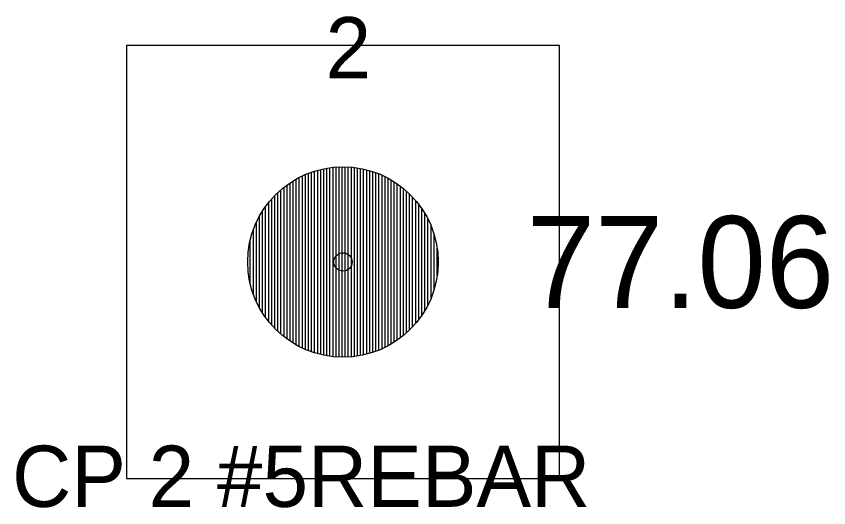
# Model space of a CAD drawing. Extents: x 2505249 to 2506333, y 912937 to 914171.
# Drawn here: x 2506319.57 to 2506332.83, y 914162.56 to 914170.59 of the extents above; entities that cross this region are included whole.
import ezdxf

# ---------------------------------------------------------------- set-up
doc = ezdxf.new("R2010")
doc.units = 0
for name, color, linetype in [('RD_HC_Survey', 7, 'Continuous'), ('RD_HC_Survey_ELEV', 7, 'Continuous'), ('RD_HC_Survey_txCode', 7, 'Continuous'), ('RD_SMD_Locator', 7, 'Continuous')]:
    doc.layers.add(name, color=color, linetype=linetype)

msp = doc.modelspace()

# ---------------------------------------------------------------- linework, layer by layer
at = {"layer": 'RD_HC_Survey'}
for p, q in [((2506324.489, 914165.072), (2506324.489, 914168.071)), ((2506324.539, 914165.06), (2506324.539, 914168.083)), ((2506324.589, 914165.049), (2506324.589, 914168.094)), ((2506324.639, 914165.039), (2506324.639, 914168.104)), ((2506324.689, 914165.031), (2506324.689, 914168.112)), ((2506324.739, 914165.025), (2506324.739, 914168.118)), ((2506324.789, 914165.021), (2506324.789, 914168.122)), ((2506324.839, 914165.018), (2506324.839, 914168.125)), ((2506324.889, 914165.017), (2506324.889, 914168.126)), ((2506324.939, 914165.017), (2506324.939, 914168.126)), ((2506324.989, 914165.019), (2506324.989, 914168.124)), ((2506325.039, 914165.023), (2506325.039, 914168.12)), ((2506325.089, 914165.028), (2506325.089, 914168.115)), ((2506325.139, 914165.035), (2506325.139, 914168.108)), ((2506325.189, 914165.044), (2506325.189, 914168.099)), ((2506325.239, 914165.054), (2506325.239, 914168.089)), ((2506325.289, 914165.066), (2506325.289, 914168.077)), ((2506324.189, 914165.189), (2506324.189, 914167.954)), ((2506324.239, 914165.165), (2506324.239, 914167.978)), ((2506324.289, 914165.142), (2506324.289, 914168.001)), ((2506324.339, 914165.122), (2506324.339, 914168.021)), ((2506324.389, 914165.104), (2506324.389, 914168.039)), ((2506324.439, 914165.087), (2506324.439, 914168.056)), ((2506325.339, 914165.08), (2506325.339, 914168.063)), ((2506325.389, 914165.096), (2506325.389, 914168.047)), ((2506325.439, 914165.113), (2506325.439, 914168.03)), ((2506325.489, 914165.132), (2506325.489, 914168.011)), ((2506325.539, 914165.154), (2506325.539, 914167.989)), ((2506325.589, 914165.177), (2506325.589, 914167.966)), ((2506325.639, 914165.203), (2506325.639, 914167.94)), ((2506323.989, 914165.312), (2506323.989, 914167.831)), ((2506324.039, 914165.278), (2506324.039, 914167.865)), ((2506324.089, 914165.246), (2506324.089, 914167.897)), ((2506324.139, 914165.216), (2506324.139, 914167.927)), ((2506325.689, 914165.231), (2506325.689, 914167.912)), ((2506325.739, 914165.262), (2506325.739, 914167.881)), ((2506325.789, 914165.296), (2506325.789, 914167.847)), ((2506325.839, 914165.332), (2506325.839, 914167.811)), ((2506323.839, 914165.436), (2506323.839, 914167.707)), ((2506323.889, 914165.391), (2506323.889, 914167.752)), ((2506323.939, 914165.35), (2506323.939, 914167.793)), ((2506325.889, 914165.371), (2506325.889, 914167.772)), ((2506325.939, 914165.414), (2506325.939, 914167.729)), ((2506325.989, 914165.461), (2506325.989, 914167.682)), ((2506323.689, 914165.598), (2506323.689, 914167.545)), ((2506323.739, 914165.539), (2506323.739, 914167.604)), ((2506323.789, 914165.485), (2506323.789, 914167.658)), ((2506326.039, 914165.513), (2506326.039, 914167.63)), ((2506326.089, 914165.569), (2506326.089, 914167.574)), ((2506323.639, 914165.664), (2506323.639, 914167.479)), ((2506326.139, 914165.631), (2506326.139, 914167.512)), ((2506326.189, 914165.701), (2506326.189, 914167.442)), ((2506323.539, 914165.822), (2506323.539, 914167.321)), ((2506323.589, 914165.737), (2506323.589, 914167.406)), ((2506326.239, 914165.78), (2506326.239, 914167.363)), ((2506323.489, 914165.921), (2506323.489, 914167.222)), ((2506326.289, 914165.872), (2506326.289, 914167.271)), ((2506326.339, 914165.981), (2506326.339, 914167.162)), ((2506323.439, 914166.043), (2506323.439, 914167.1)), ((2506326.389, 914166.122), (2506326.389, 914167.021)), ((2506323.389, 914166.21), (2506323.389, 914166.933)), ((2506326.439, 914166.346), (2506326.439, 914166.797))]:
    msp.add_line(p, q, dxfattribs=at)
msp.add_lwpolyline([(2506328.437, 914170.107), (2506321.366, 914170.107), (2506321.366, 914163.036), (2506328.437, 914163.036)], close=True, dxfattribs=at)
msp.add_circle((2506324.901, 914166.572), 1.555, dxfattribs=at)
at = {"layer": 'RD_SMD_Locator'}
msp.add_circle((2506324.901, 914166.572), 0.15, dxfattribs=at)

# ---------------------------------------------------------------- texts
at = {"layer": 'RD_HC_Survey_ELEV'}
msp.add_text('77.06', height=1.5, dxfattribs=at).set_placement((2506327.901, 914165.822))
at = {"layer": 'RD_HC_Survey_txCode'}
for s, p in [('2', (2506324.618, 914169.572)), ('CP 2 #5REBAR', (2506319.5, 914162.572))]:
    msp.add_text(s, height=1, dxfattribs=at).set_placement(p)

doc.saveas('drawing.dxf')
